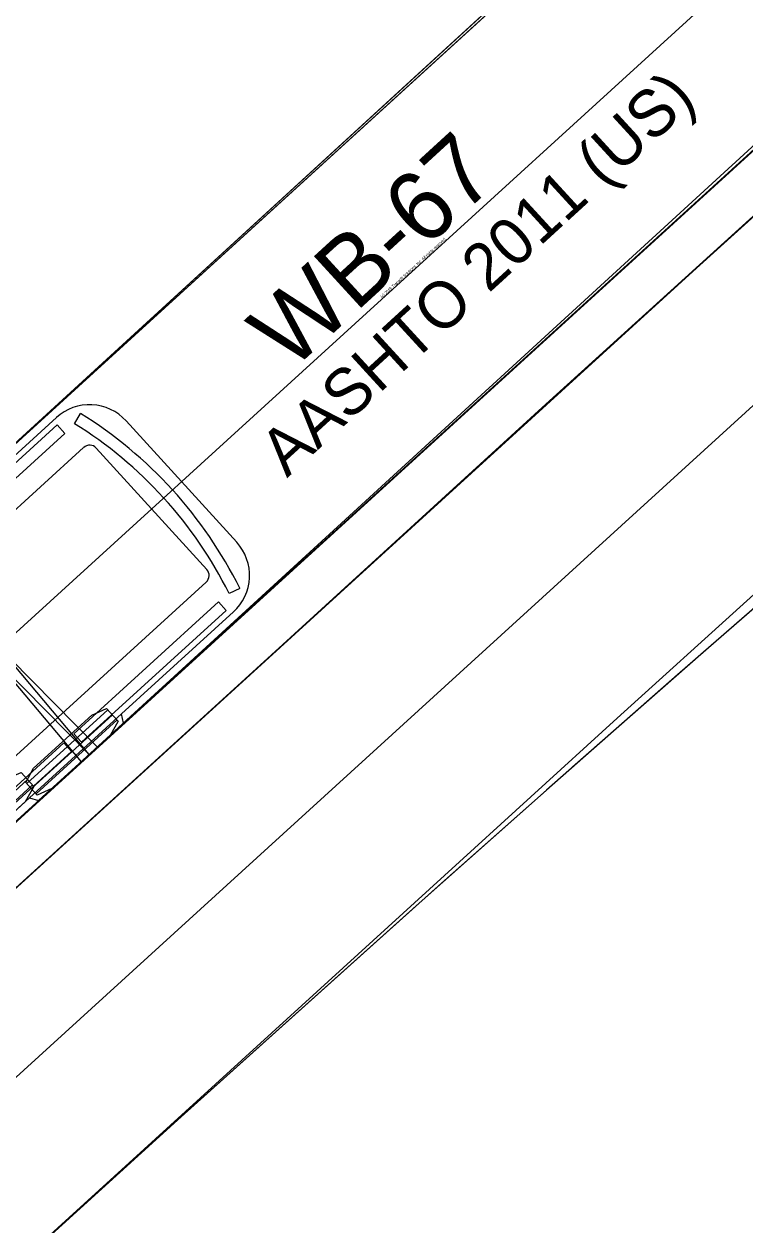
# Model space of a CAD drawing. Extents: x 1639988 to 1641860, y 841974 to 844187.
# Drawn here: x 1640055.18 to 1640077.12, y 843432.19 to 843468.7 of the extents above; entities that cross this region are included whole.
import ezdxf

# ---------------------------------------------------------------- set-up
doc = ezdxf.new("R2010")
doc.units = 0
for name, color, linetype in [('Scratch_Level_1', 7, 'Continuous'), ('Scratch_Level_2', 7, 'Continuous'), ('Scratch_Level_3', 7, 'Continuous'), ('Scratch_Level_4', 7, 'Continuous'), ('Scratch_Level_5', 7, 'Continuous'), ('Scratch_Level_6', 7, 'Continuous')]:
    doc.layers.add(name, color=color, linetype=linetype)

msp = doc.modelspace()

# ---------------------------------------------------------------- linework, layer by layer
at = {"layer": 'Scratch_Level_1'}
for p, q in [((1640142.045, 843529.549), (1640035.579, 843432.551)), ((1640042.68, 843425.492), (1640087.369, 843466.207)), ((1640052.575, 843443.245), (1640055.286, 843445.715)), ((1640052.73, 843443.076), (1640055.44, 843445.545))]:
    msp.add_line(p, q, dxfattribs=at)
for points in [[(1640146.184, 843527.571), (1640130.418, 843513.153), (1640087.006, 843473.626), (1640081.172, 843479.499), (1640086.514, 843473.178), (1640050.652, 843440.523), (1640050.246, 843440.503), (1640035.316, 843426.9), (1640029.928, 843432.814), (1640044.854, 843446.413), (1640044.91, 843446.791), (1640091.971, 843489.915), (1640107.666, 843504.355), (1640123.316, 843518.836), (1640131.115, 843526.099), (1640138.892, 843533.382)], [(1639988.552, 843381.927), (1640075.48, 843461.123), (1640079.453, 843464.719), (1640083.447, 843468.294), (1640087.471, 843471.841), (1640091.525, 843475.35), (1640093.544, 843477.118), (1640095.576, 843478.872), (1640099.681, 843482.333), (1640103.837, 843485.735), (1640108.041, 843489.076), (1640112.291, 843492.356), (1640116.585, 843495.576), (1640120.921, 843498.735), (1640125.299, 843501.833), (1640129.717, 843504.87), (1640134.175, 843507.846), (1640138.671, 843510.76)], [(1640137.628, 843497.624), (1640133.283, 843494.579), (1640128.957, 843491.512), (1640124.652, 843488.422), (1640120.37, 843485.306), (1640116.113, 843482.163), (1640111.883, 843478.991), (1640107.682, 843475.786), (1640103.511, 843472.549), (1640099.37, 843469.276), (1640095.259, 843465.968), (1640091.175, 843462.622), (1640087.115, 843459.239), (1640083.077, 843455.821), (1640079.06, 843452.372), (1640075.061, 843448.895), (1640071.078, 843445.391), (1640067.108, 843441.865), (1640059.196, 843434.757), (1640051.304, 843427.597), (1639994.167, 843375.544), (1639988.442, 843381.828), (1639988.552, 843381.927), (1639988.552, 843381.927)], [(1640083.953, 843482.528), (1640083.938, 843482.544), (1640083.886, 843482.497), (1640079.707, 843478.669), (1640044.91, 843446.791), (1640047.781, 843443.657), (1640050.652, 843440.523), (1640085.449, 843472.402), (1640089.627, 843476.23), (1640089.679, 843476.278), (1640089.664, 843476.294)]]:
    msp.add_lwpolyline(points, dxfattribs=at)
msp.add_lwpolyline([(1640052.768, 843443.034), (1640052.383, 843443.457), (1640052.646, 843443.93), (1640054.598, 843445.708), (1640055.093, 843445.926), (1640055.478, 843445.503), (1640055.215, 843445.03), (1640053.264, 843443.252)], close=True, dxfattribs=at)
at = {"layer": 'Scratch_Level_2'}
for p, q in [((1640142.045, 843529.549), (1640035.579, 843432.551)), ((1640042.68, 843425.492), (1640087.369, 843466.207)), ((1640052.575, 843443.245), (1640055.286, 843445.715)), ((1640052.73, 843443.076), (1640055.44, 843445.545))]:
    msp.add_line(p, q, dxfattribs=at)
for points in [[(1640145.443, 843526.895), (1640129.676, 843512.479), (1640087.006, 843473.626), (1640081.172, 843479.5), (1640086.514, 843473.178), (1640050.652, 843440.523), (1640050.246, 843440.502), (1640035.316, 843426.9), (1640029.928, 843432.814), (1640044.854, 843446.413), (1640044.91, 843446.791), (1640091.974, 843489.913), (1640107.671, 843504.351), (1640123.323, 843518.83), (1640131.124, 843526.091), (1640138.904, 843533.372)], [(1640083.955, 843482.526), (1640083.94, 843482.542), (1640083.888, 843482.495), (1640079.709, 843478.667), (1640044.91, 843446.791), (1640047.781, 843443.657), (1640050.652, 843440.523), (1640085.45, 843472.399), (1640089.629, 843476.228), (1640089.681, 843476.276), (1640089.666, 843476.292)]]:
    msp.add_lwpolyline(points, dxfattribs=at)
msp.add_lwpolyline([(1640052.768, 843443.034), (1640052.383, 843443.457), (1640052.646, 843443.93), (1640054.598, 843445.708), (1640055.093, 843445.926), (1640055.478, 843445.503), (1640055.215, 843445.03), (1640053.264, 843443.252)], close=True, dxfattribs=at)
at = {"layer": 'Scratch_Level_3'}
for p, q in [((1640142.045, 843529.549), (1640035.579, 843432.551)), ((1640042.68, 843425.492), (1640087.369, 843466.207)), ((1640052.575, 843443.245), (1640055.286, 843445.715)), ((1640052.73, 843443.076), (1640055.44, 843445.545))]:
    msp.add_line(p, q, dxfattribs=at)
for points in [[(1640146.917, 843528.25), (1640131.155, 843513.828), (1640087.006, 843473.626), (1640081.173, 843479.5), (1640086.512, 843473.177), (1640050.651, 843440.523), (1640050.246, 843440.502), (1640035.316, 843426.9), (1640029.934, 843432.819), (1640044.854, 843446.413), (1640044.91, 843446.791), (1640092.221, 843490.137), (1640107.918, 843504.575), (1640123.57, 843519.054), (1640131.372, 843526.315), (1640139.151, 843533.595)], [(1639988.549, 843381.924), (1640075.534, 843461.172), (1640079.512, 843464.772), (1640083.513, 843468.352), (1640087.542, 843471.903), (1640091.604, 843475.42), (1640093.625, 843477.189), (1640095.658, 843478.942), (1640099.765, 843482.403), (1640103.924, 843485.805), (1640108.132, 843489.147), (1640112.386, 843492.429), (1640116.685, 843495.651), (1640121.027, 843498.812), (1640125.411, 843501.911), (1640129.834, 843504.95), (1640134.297, 843507.926), (1640138.798, 843510.841)], [(1640138.602, 843498.073), (1640134.234, 843495.066), (1640129.887, 843492.035), (1640125.564, 843488.978), (1640121.266, 843485.892), (1640116.996, 843482.774), (1640112.756, 843479.624), (1640108.547, 843476.438), (1640104.369, 843473.216), (1640100.224, 843469.955), (1640096.105, 843466.653), (1640092.009, 843463.31), (1640087.938, 843459.929), (1640083.891, 843456.514), (1640079.864, 843453.066), (1640075.856, 843449.59), (1640071.865, 843446.086), (1640067.887, 843442.559), (1640059.961, 843435.448), (1640052.057, 843428.282), (1639994.167, 843375.544), (1639988.442, 843381.828), (1639988.549, 843381.924), (1639988.549, 843381.924)], [(1640083.956, 843482.526), (1640083.941, 843482.542), (1640083.889, 843482.494), (1640079.71, 843478.666), (1640044.91, 843446.791), (1640047.781, 843443.657), (1640050.651, 843440.523), (1640085.451, 843472.399), (1640089.63, 843476.227), (1640089.682, 843476.275), (1640089.667, 843476.291)]]:
    msp.add_lwpolyline(points, dxfattribs=at)
msp.add_lwpolyline([(1640052.768, 843443.034), (1640052.383, 843443.457), (1640052.646, 843443.93), (1640054.598, 843445.708), (1640055.093, 843445.926), (1640055.478, 843445.503), (1640055.215, 843445.03), (1640053.264, 843443.252)], close=True, dxfattribs=at)
at = {"layer": 'Scratch_Level_4'}
for p, q in [((1640142.045, 843529.549), (1640035.579, 843432.551)), ((1640042.68, 843425.492), (1640087.369, 843466.207)), ((1640056.997, 843455.813), (1640030.068, 843431.276)), ((1640060.745, 843452.101), (1640057.379, 843455.796)), ((1640033.798, 843427.182), (1640060.728, 843451.72)), ((1640055.267, 843445.587), (1640057.731, 843447.832)), ((1640055.352, 843445.158), (1640058.15, 843447.708)), ((1640055.408, 843445.433), (1640057.872, 843447.678)), ((1640055.548, 843445.279), (1640058.012, 843447.524))]:
    msp.add_line(p, q, dxfattribs=at)
for points in [[(1640142.303, 843523.851), (1640126.468, 843509.527), (1640094.883, 843480.817), (1640057.415, 843446.694), (1640051.444, 843452.752), (1640056.922, 843446.245), (1640033.267, 843424.695), (1640027.542, 843430.978), (1640090.865, 843488.687), (1640106.625, 843503.067), (1640122.367, 843517.461), (1640138.069, 843531.886)], [(1640015.629, 843406.597), (1640063.06, 843449.817), (1640070.951, 843457.031), (1640078.888, 843464.23), (1640090.806, 843475.083), (1640092.811, 843476.877), (1640094.833, 843478.655), (1640096.869, 843480.416), (1640098.92, 843482.162), (1640100.985, 843483.892), (1640103.064, 843485.606), (1640105.157, 843487.304), (1640107.263, 843488.987), (1640111.513, 843492.306), (1640115.812, 843495.563), (1640120.156, 843498.756), (1640124.538, 843501.882), (1640128.957, 843504.942), (1640133.413, 843507.935), (1640137.905, 843510.864)], [(1640139.344, 843500.335), (1640134.956, 843497.359), (1640130.598, 843494.356), (1640126.277, 843491.318), (1640121.995, 843488.234), (1640117.753, 843485.098), (1640113.548, 843481.908), (1640109.381, 843478.668), (1640105.25, 843475.378), (1640101.155, 843472.039), (1640097.092, 843468.655), (1640093.061, 843465.228), (1640089.058, 843461.761), (1640085.078, 843458.257), (1640081.118, 843454.721), (1640073.228, 843447.575), (1640021.148, 843400.126), (1640015.423, 843406.409), (1640015.629, 843406.597), (1640015.629, 843406.597)], [(1640056.716, 843456.534), (1640056.9, 843456.845)], [(1640056.169, 843456.722), (1640052.764, 843453.619), (1640052.489, 843453.709), (1640049.902, 843451.351), (1640049.965, 843451.069), (1640034.403, 843436.89), (1640034.01, 843436.871), (1640031.423, 843434.514), (1640031.367, 843434.124)], [(1640061.654, 843452.93), (1640058.288, 843456.624)], [(1640061.746, 843451.527), (1640061.42, 843451.373)], [(1640034.626, 843426.273), (1640036.754, 843428.212), (1640037.147, 843428.231), (1640039.735, 843430.588), (1640039.79, 843430.978), (1640055.352, 843445.158), (1640055.627, 843445.068), (1640058.214, 843447.426), (1640058.15, 843447.708), (1640061.556, 843450.811)]]:
    msp.add_lwpolyline(points, dxfattribs=at)
for points in [[(1640056.428, 843456.243), (1640056.195, 843456.498), (1640051.79, 843452.484), (1640052.023, 843452.23)], [(1640061.103, 843451.113), (1640061.335, 843450.858), (1640056.93, 843446.843), (1640056.698, 843447.099)], [(1640055.583, 843445.24), (1640055.233, 843445.625), (1640055.472, 843446.055), (1640057.246, 843447.671), (1640057.696, 843447.87), (1640058.047, 843447.485), (1640057.807, 843447.055), (1640056.033, 843445.439)], [(1640056.395, 843446.823), (1640056.628, 843446.568), (1640052.222, 843442.554), (1640051.991, 843442.81)]]:
    msp.add_lwpolyline(points, close=True, dxfattribs=at)
for centre, radius, start, end in [((1640057.18, 843455.614), 1.5, 42.3391, 132.3391), ((1640050.033, 843445.722), 13.073, 26.3661, 58.312), ((1640050.033, 843445.722), 12.711, 26.3963, 58.2818), ((1640057.18, 843455.614), 0.27, 42.3391, 132.3391), ((1640060.545, 843451.919), 1.5, 312.3391, 42.3391), ((1640060.545, 843451.919), 0.27, 312.3391, 42.3391)]:
    msp.add_arc(centre, radius, start, end, dxfattribs=at)
at = {"layer": 'Scratch_Level_5'}
for p, q in [((1640142.045, 843529.549), (1640035.579, 843432.551)), ((1640042.68, 843425.492), (1640087.369, 843466.207)), ((1640056.997, 843455.813), (1640030.068, 843431.276)), ((1640060.745, 843452.101), (1640057.379, 843455.796)), ((1640033.798, 843427.182), (1640060.728, 843451.72)), ((1640055.267, 843445.587), (1640057.731, 843447.832)), ((1640055.352, 843445.158), (1640058.15, 843447.708)), ((1640055.408, 843445.433), (1640057.872, 843447.678)), ((1640055.548, 843445.279), (1640058.012, 843447.524))]:
    msp.add_line(p, q, dxfattribs=at)
for points in [[(1640140.818, 843522.508), (1640124.986, 843508.182), (1640093.404, 843479.47), (1640033.267, 843424.695), (1640027.542, 843430.978), (1640051.195, 843452.53), (1640057.167, 843446.472), (1640051.688, 843452.979), (1640083.229, 843481.724), (1640114.745, 843510.486), (1640130.471, 843524.893), (1640138.314, 843532.112)], [(1640015.633, 843406.6), (1640063.06, 843449.817), (1640070.951, 843457.031), (1640078.888, 843464.23), (1640090.806, 843475.083), (1640092.811, 843476.877), (1640094.833, 843478.655), (1640096.869, 843480.416), (1640098.92, 843482.162), (1640100.985, 843483.892), (1640103.064, 843485.606), (1640105.157, 843487.304), (1640107.263, 843488.987), (1640111.513, 843492.306), (1640115.812, 843495.563), (1640120.156, 843498.756), (1640124.538, 843501.882), (1640128.957, 843504.942), (1640133.413, 843507.935), (1640137.905, 843510.864)], [(1640139.344, 843500.335), (1640134.956, 843497.359), (1640130.598, 843494.356), (1640126.277, 843491.318), (1640121.995, 843488.234), (1640117.753, 843485.098), (1640113.548, 843481.908), (1640109.381, 843478.668), (1640105.25, 843475.378), (1640101.155, 843472.039), (1640097.092, 843468.655), (1640093.061, 843465.228), (1640089.058, 843461.761), (1640085.078, 843458.257), (1640081.118, 843454.721), (1640073.228, 843447.575), (1640021.148, 843400.126), (1640015.423, 843406.409), (1640015.633, 843406.6), (1640015.633, 843406.6)], [(1640056.716, 843456.534), (1640056.9, 843456.845)], [(1640056.169, 843456.722), (1640052.764, 843453.619), (1640052.489, 843453.709), (1640049.902, 843451.351), (1640049.965, 843451.069), (1640034.403, 843436.89), (1640034.01, 843436.871), (1640031.423, 843434.514), (1640031.367, 843434.124)], [(1640061.654, 843452.93), (1640058.288, 843456.624)], [(1640061.746, 843451.527), (1640061.42, 843451.373)], [(1640034.626, 843426.273), (1640036.754, 843428.212), (1640037.147, 843428.231), (1640039.735, 843430.588), (1640039.79, 843430.978), (1640055.352, 843445.158), (1640055.627, 843445.068), (1640058.214, 843447.426), (1640058.15, 843447.708), (1640061.556, 843450.811)]]:
    msp.add_lwpolyline(points, dxfattribs=at)
for points in [[(1640056.428, 843456.243), (1640056.195, 843456.498), (1640051.79, 843452.484), (1640052.023, 843452.23)], [(1640061.103, 843451.113), (1640061.335, 843450.858), (1640056.93, 843446.843), (1640056.698, 843447.099)], [(1640055.583, 843445.24), (1640055.233, 843445.625), (1640055.472, 843446.055), (1640057.246, 843447.671), (1640057.696, 843447.87), (1640058.047, 843447.485), (1640057.807, 843447.055), (1640056.033, 843445.439)], [(1640056.395, 843446.823), (1640056.628, 843446.568), (1640052.222, 843442.554), (1640051.991, 843442.81)]]:
    msp.add_lwpolyline(points, close=True, dxfattribs=at)
for centre, radius, start, end in [((1640057.18, 843455.614), 1.5, 42.3391, 132.3391), ((1640050.033, 843445.722), 13.073, 26.3661, 58.312), ((1640050.033, 843445.722), 12.711, 26.3963, 58.2818), ((1640057.18, 843455.614), 0.27, 42.3391, 132.3391), ((1640060.545, 843451.919), 1.5, 312.3391, 42.3391), ((1640060.545, 843451.919), 0.27, 312.3391, 42.3391)]:
    msp.add_arc(centre, radius, start, end, dxfattribs=at)
at = {"layer": 'Scratch_Level_6'}
for p, q in [((1640142.045, 843529.549), (1640035.579, 843432.551)), ((1640042.68, 843425.492), (1640087.369, 843466.207)), ((1640056.997, 843455.813), (1640030.068, 843431.276)), ((1640060.745, 843452.101), (1640057.379, 843455.796)), ((1640033.798, 843427.182), (1640060.728, 843451.72)), ((1640055.267, 843445.587), (1640057.731, 843447.832)), ((1640055.352, 843445.158), (1640058.15, 843447.708)), ((1640055.408, 843445.433), (1640057.872, 843447.678)), ((1640055.548, 843445.279), (1640058.012, 843447.524))]:
    msp.add_line(p, q, dxfattribs=at)
for points in [[(1640140.818, 843522.508), (1640124.986, 843508.182), (1640093.404, 843479.47), (1640057.415, 843446.694), (1640051.444, 843452.752), (1640056.922, 843446.245), (1640033.267, 843424.695), (1640027.542, 843430.978), (1640090.865, 843488.687), (1640106.625, 843503.067), (1640122.367, 843517.461), (1640138.069, 843531.886)], [(1640015.614, 843406.583), (1640063.06, 843449.817), (1640070.951, 843457.031), (1640078.888, 843464.23), (1640090.806, 843475.083), (1640092.811, 843476.877), (1640094.833, 843478.655), (1640096.869, 843480.416), (1640098.92, 843482.162), (1640100.985, 843483.892), (1640103.064, 843485.606), (1640105.157, 843487.304), (1640107.263, 843488.987), (1640111.513, 843492.306), (1640115.812, 843495.563), (1640120.156, 843498.756), (1640124.538, 843501.882), (1640128.957, 843504.942), (1640133.413, 843507.935), (1640137.905, 843510.864)], [(1640139.344, 843500.335), (1640134.956, 843497.359), (1640130.598, 843494.356), (1640126.277, 843491.318), (1640121.995, 843488.234), (1640117.753, 843485.098), (1640113.548, 843481.908), (1640109.381, 843478.668), (1640105.25, 843475.378), (1640101.155, 843472.039), (1640097.092, 843468.655), (1640093.061, 843465.228), (1640089.058, 843461.761), (1640085.078, 843458.257), (1640081.118, 843454.721), (1640073.228, 843447.575), (1640021.148, 843400.126), (1640015.423, 843406.409), (1640015.614, 843406.583), (1640015.614, 843406.583)], [(1640056.716, 843456.534), (1640056.9, 843456.845)], [(1640056.169, 843456.722), (1640052.764, 843453.619), (1640052.489, 843453.709), (1640049.902, 843451.351), (1640049.965, 843451.069), (1640034.403, 843436.89), (1640034.01, 843436.871), (1640031.423, 843434.514), (1640031.367, 843434.124)], [(1640061.654, 843452.93), (1640058.288, 843456.624)], [(1640061.746, 843451.527), (1640061.42, 843451.373)], [(1640034.626, 843426.273), (1640036.754, 843428.212), (1640037.147, 843428.231), (1640039.735, 843430.588), (1640039.79, 843430.978), (1640055.352, 843445.158), (1640055.627, 843445.068), (1640058.214, 843447.426), (1640058.15, 843447.708), (1640061.556, 843450.811)]]:
    msp.add_lwpolyline(points, dxfattribs=at)
for points in [[(1640056.428, 843456.243), (1640056.195, 843456.498), (1640051.79, 843452.484), (1640052.023, 843452.23)], [(1640061.103, 843451.113), (1640061.335, 843450.858), (1640056.93, 843446.843), (1640056.698, 843447.099)], [(1640055.583, 843445.24), (1640055.233, 843445.625), (1640055.472, 843446.055), (1640057.246, 843447.671), (1640057.696, 843447.87), (1640058.047, 843447.485), (1640057.807, 843447.055), (1640056.033, 843445.439)], [(1640056.395, 843446.823), (1640056.628, 843446.568), (1640052.222, 843442.554), (1640051.991, 843442.81)]]:
    msp.add_lwpolyline(points, close=True, dxfattribs=at)
for centre, radius, start, end in [((1640057.18, 843455.614), 1.5, 42.3391, 132.3391), ((1640050.033, 843445.722), 13.073, 26.3661, 58.312), ((1640050.033, 843445.722), 12.711, 26.3963, 58.2818), ((1640057.18, 843455.614), 0.27, 42.3391, 132.3391), ((1640060.545, 843451.919), 1.5, 312.3391, 42.3391), ((1640060.545, 843451.919), 0.27, 312.3391, 42.3391)]:
    msp.add_arc(centre, radius, start, end, dxfattribs=at)

# ---------------------------------------------------------------- texts
at = {"layer": 'Scratch_Level_1'}
for s, height, p in [('AASHTO 2011 (US)', 1.41667, (1640063.184, 843454.876)), ('WB-67', 2.125, (1640063.289, 843458.095)), ('(c) 2019 Transoft Solutions, Inc. All rights reserved.', 0.085, (1640066.072, 843460.356))]:
    msp.add_text(s, height=height, rotation=42.4936, dxfattribs=at).set_placement(p)
at = {"layer": 'Scratch_Level_2'}
for s, height, p in [('AASHTO 2011 (US)', 1.41667, (1640063.184, 843454.876)), ('WB-67', 2.125, (1640063.29, 843458.094)), ('(c) 2019 Transoft Solutions, Inc. All rights reserved.', 0.085, (1640066.073, 843460.355))]:
    msp.add_text(s, height=height, rotation=42.4902, dxfattribs=at).set_placement(p)
at = {"layer": 'Scratch_Level_3'}
for s, height, p in [('AASHTO 2011 (US)', 1.41667, (1640063.184, 843454.875)), ('WB-67', 2.125, (1640063.29, 843458.094)), ('(c) 2019 Transoft Solutions, Inc. All rights reserved.', 0.085, (1640066.073, 843460.355))]:
    msp.add_text(s, height=height, rotation=42.4887, dxfattribs=at).set_placement(p)

doc.saveas('drawing.dxf')
